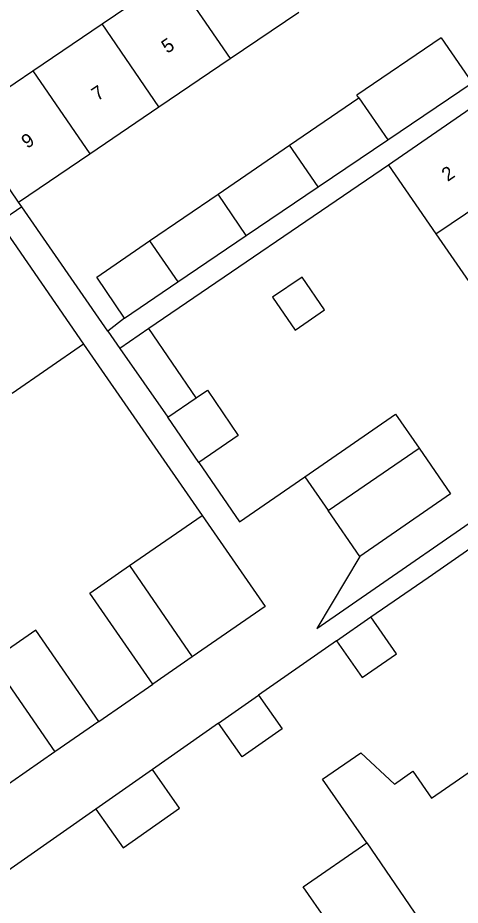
# Model space of a CAD drawing. Extents: x 137999 to 141000, y 397500 to 400501.
# Drawn here: x 138132.3 to 138164.6, y 399868.5 to 399933.3 of the extents above; entities that cross this region are included whole.
import ezdxf

# ---------------------------------------------------------------- set-up
doc = ezdxf.new("R2010")
doc.units = 0
for name, color, linetype in [('gg-afsc-erfafscheiding', 7, 'Continuous'), ('gg-afsc-muur', 7, 'Continuous'), ('gg-anno-huisnummerreeks BGT', 7, 'Continuous'), ('gg-bbg-bijgebouw', 7, 'Continuous'), ('gg-bbg-gedigitaliseerde bebouwing', 7, 'Continuous'), ('gg-bbg-gedigitaliseerde bijgebouw', 7, 'Continuous'), ('gg-bbg-hoofdgebouw', 7, 'Continuous'), ('gg-bbg-tussenscheiding', 7, 'Continuous'), ('gt-grn-weggrens', 7, 'Continuous')]:
    doc.layers.add(name, color=color, linetype=linetype)

msp = doc.modelspace()

# ---------------------------------------------------------------- linework, layer by layer
at = {"layer": 'gg-afsc-erfafscheiding'}
for p, q in [((138159.36, 399922.531), (138141.839, 399910.587)), ((138132.576, 399919.474), (138132.33, 399919.83)), ((138138.851, 399910.4), (138132.576, 399919.474)), ((138140.064, 399911.35), (138138.851, 399910.4)), ((138138.851, 399910.4), (138139.72, 399909.142)), ((138137.09, 399909.442), (138145.738, 399896.935)), ((138158.07, 399889.532), (138162.241, 399892.403)), ((138155.567, 399887.785), (138149.866, 399883.792)), ((138138.21, 399881.886), (138142.137, 399884.602)), ((138146.948, 399881.748), (138142.118, 399878.365))]:
    msp.add_line(p, q, dxfattribs=at)
for points in [[(138145.494, 399900.811), (138148.484, 399896.468), (138153.242, 399899.759)], [(138157.271, 399893.932), (138154.118, 399888.663), (138169.814, 399899.547)], [(138137.989, 399875.474), (138118.988, 399862.166), (138125.991, 399852.029)]]:
    msp.add_lwpolyline(points, dxfattribs=at)
at = {"layer": 'gg-afsc-muur'}
msp.add_lwpolyline([(138162.241, 399892.403), (138165.926, 399894.959), (138166.183, 399894.589)], dxfattribs=at)
at = {"layer": 'gg-bbg-bijgebouw'}
for p, q in [((138163.21, 399931.84), (138165.46, 399928.54)), ((138140.064, 399911.35), (138138.041, 399914.337)), ((138155.567, 399887.785), (138158.07, 399889.532))]:
    msp.add_line(p, q, dxfattribs=at)
at = {"layer": 'gg-bbg-gedigitaliseerde bebouwing'}
for p, q in [((138165.32, 399926.65), (138159.36, 399922.531)), ((138159.36, 399922.531), (138162.821, 399917.5)), ((138130.93, 399918.35), (138137.09, 399909.442)), ((138162.821, 399917.5), (138166.305, 399912.434)), ((138137.09, 399909.442), (138131.871, 399905.833))]:
    msp.add_line(p, q, dxfattribs=at)
for points in [[(138157.77, 399873.004), (138154.542, 399877.672), (138157.327, 399879.598), (138159.798, 399877.298), (138161.14, 399878.241), (138162.5, 399876.275), (138165.567, 399878.396)], [(138151.681, 399865.115), (138154.852, 399867.308), (138153.131, 399869.796), (138157.77, 399873.004)]]:
    msp.add_lwpolyline(points, dxfattribs=at)
at = {"layer": 'gg-bbg-gedigitaliseerde bijgebouw'}
for p, q in [((138163.21, 399931.84), (138157.043, 399927.639)), ((138159.316, 399924.381), (138165.46, 399928.54)), ((138152.128, 399923.984), (138157.179, 399927.444)), ((138157.179, 399927.444), (138157.043, 399927.639)), ((138154.219, 399920.931), (138159.316, 399924.381)), ((138146.908, 399920.409), (138152.128, 399923.984)), ((138148.968, 399917.377), (138154.219, 399920.931)), ((138141.91, 399916.986), (138146.908, 399920.409)), ((138138.041, 399914.337), (138141.91, 399916.986)), ((138143.967, 399913.992), (138148.968, 399917.377)), ((138140.064, 399911.35), (138143.967, 399913.992)), ((138141.839, 399910.587), (138139.72, 399909.142)), ((138145.3, 399905.524), (138141.839, 399910.587)), ((138139.72, 399909.142), (138143.236, 399904.113)), ((138145.494, 399900.811), (138143.236, 399904.113)), ((138153.242, 399899.759), (138154.944, 399897.298)), ((138140.45, 399893.278), (138145.738, 399896.935)), ((138157.271, 399893.932), (138154.944, 399897.298)), ((138145.024, 399886.598), (138142.137, 399884.602)), ((138146.948, 399881.748), (138149.866, 399883.792)), ((138138.21, 399881.886), (138134.985, 399879.656)), ((138134.985, 399879.656), (138130.005, 399876.213)), ((138142.118, 399878.365), (138137.989, 399875.474))]:
    msp.add_line(p, q, dxfattribs=at)
for points in [[(138152.531, 399910.467), (138154.692, 399911.944), (138153.05, 399914.347), (138150.888, 399912.87), (138152.531, 399910.467)], [(138145.3, 399905.524), (138146.125, 399906.088), (138148.383, 399902.786), (138145.494, 399900.811)], [(138153.242, 399899.759), (138159.865, 399904.338), (138161.591, 399901.842)], [(138161.591, 399901.842), (138163.894, 399898.512), (138157.271, 399893.932)], [(138145.738, 399896.935), (138150.343, 399890.276), (138145.024, 399886.598)], [(138142.137, 399884.602), (138137.532, 399891.261), (138140.45, 399893.278)], [(138155.567, 399887.785), (138157.428, 399885.094), (138159.939, 399886.83), (138158.07, 399889.532)], [(138138.21, 399881.886), (138133.605, 399888.546), (138130.395, 399886.326)], [(138149.866, 399883.792), (138151.587, 399881.335), (138148.669, 399879.291), (138146.948, 399881.748)], [(138137.989, 399875.474), (138139.969, 399872.647), (138144.098, 399875.539), (138142.118, 399878.365)]]:
    msp.add_lwpolyline(points, dxfattribs=at)
at = {"layer": 'gg-bbg-hoofdgebouw'}
for p, q in [((138138.447, 399932.859), (138143.637, 399936.384)), ((138147.792, 399930.317), (138152.803, 399933.715)), ((138133.37, 399929.411), (138138.447, 399932.859)), ((138142.578, 399926.781), (138147.792, 399930.317)), ((138128.254, 399925.936), (138133.37, 399929.411)), ((138137.531, 399923.357), (138142.578, 399926.781)), ((138132.33, 399919.83), (138137.531, 399923.357))]:
    msp.add_line(p, q, dxfattribs=at)
msp.add_lwpolyline([(138132.33, 399919.83), (138128.2, 399925.9), (138128.254, 399925.936)], dxfattribs=at)
at = {"layer": 'gg-bbg-tussenscheiding'}
for p, q in [((138143.637, 399936.384), (138147.792, 399930.317)), ((138142.578, 399926.781), (138138.447, 399932.859)), ((138133.37, 399929.411), (138137.531, 399923.357)), ((138157.179, 399927.444), (138159.316, 399924.381)), ((138154.219, 399920.931), (138152.128, 399923.984)), ((138162.821, 399917.5), (138168.802, 399921.588)), ((138148.968, 399917.377), (138146.908, 399920.409)), ((138141.91, 399916.986), (138143.967, 399913.992)), ((138143.236, 399904.113), (138145.3, 399905.524)), ((138154.944, 399897.298), (138161.591, 399901.842)), ((138140.45, 399893.278), (138145.024, 399886.598)), ((138130.395, 399886.326), (138134.985, 399879.656)), ((138157.77, 399873.004), (138162.654, 399865.899))]:
    msp.add_line(p, q, dxfattribs=at)
at = {"layer": 'gt-grn-weggrens'}
msp.add_line((138132.576, 399919.474), (138130.93, 399918.35), dxfattribs=at)

# ---------------------------------------------------------------- texts
at = {"layer": 'gg-anno-huisnummerreeks BGT'}
for s, rotation, p in [('5', 34.2, (138143.201, 399930.648)), ('7', 34.2, (138138.101, 399927.184)), ('9', 34.2, (138132.974, 399923.702)), ('2', 34.5, (138163.677, 399921.295))]:
    msp.add_text(s, height=1, rotation=rotation, dxfattribs=at).set_placement(p)

doc.saveas('drawing.dxf')
